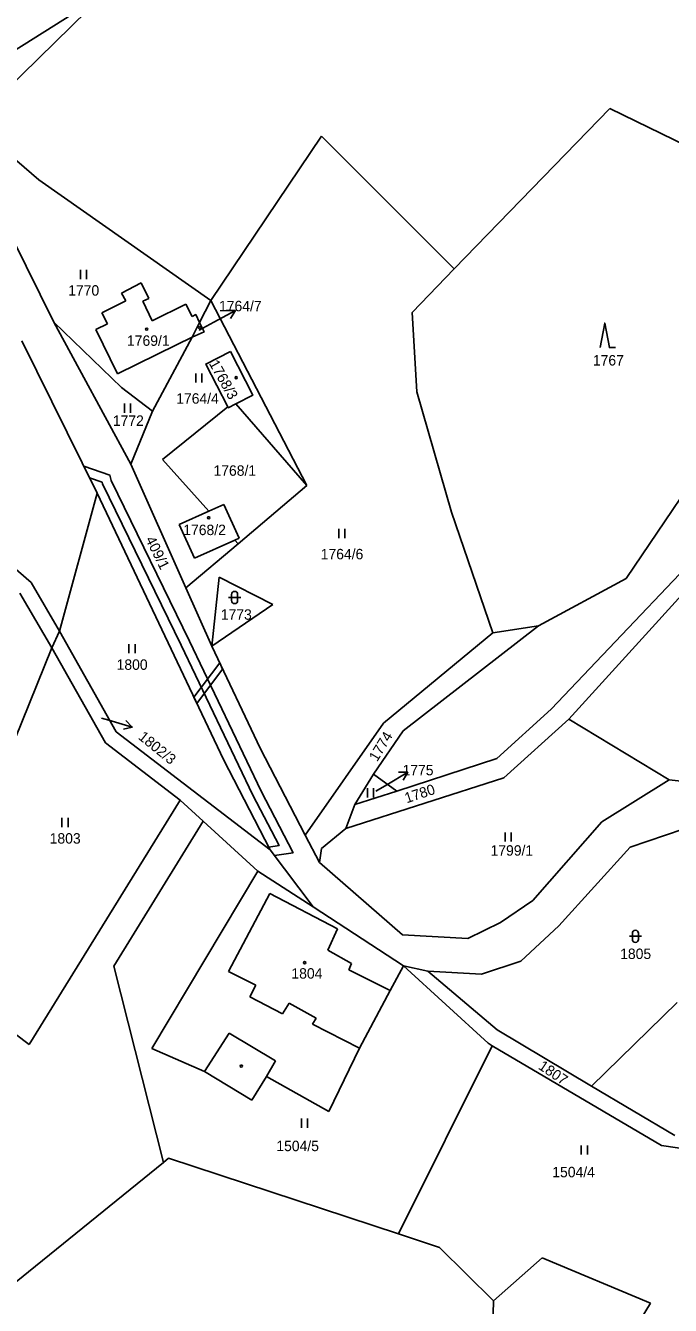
# Model space of a CAD drawing. Extents: x -670359 to -668019, y -978807 to -976674.
# Drawn here: x -669006.2 to -668901.1, y -978516 to -978307.2 of the extents above; entities that cross this region are included whole.
import ezdxf

# ---------------------------------------------------------------- set-up
doc = ezdxf.new("R2010")
doc.units = 0
for name, color, linetype in [('Hranice parcel', 7, 'Continuous'), ('Parcelní čísla', 7, 'Continuous'), ('Vnitřní kresba', 7, 'Continuous'), ('Věcná břemena k části', 7, 'Continuous'), ('Značky budov', 7, 'Continuous'), ('Značky kultur', 7, 'Continuous')]:
    doc.layers.add(name, color=color, linetype=linetype)

msp = doc.modelspace()

# ---------------------------------------------------------------- linework, layer by layer
at = {"layer": 'Hranice parcel'}
for p, q in [((-668976.34, -978386.39), (-668973.88, -978385.28)), ((-668973.88, -978385.28), (-668971.4, -978390.78)), ((-668981.19, -978388.58), (-668976.34, -978386.39)), ((-668978.67, -978394.06), (-668981.19, -978388.58)), ((-668972.11, -978391.1), (-668978.67, -978394.06)), ((-668971.4, -978390.78), (-668972.11, -978391.1)), ((-668981, -978433.55), (-668977.28, -978436.95)), ((-668977.28, -978436.95), (-668991.85, -978460.6)), ((-668977.28, -978436.95), (-668968.34, -978445.1)), ((-668991.85, -978460.6), (-668983.76, -978492.64)), ((-668930.12, -978473.61), (-668930.81, -978473.2)), ((-668945.41, -978504.31), (-668930.12, -978473.61)), ((-668930.12, -978473.61), (-668902.52, -978489.86)), ((-668983.76, -978492.64), (-668982.92, -978491.96)), ((-668982.92, -978491.96), (-668945.41, -978504.31)), ((-668983.76, -978492.64), (-669008.9, -978513.02)), ((-668945.41, -978504.31), (-668938.75, -978506.5))]:
    msp.add_line(p, q, dxfattribs=at)
for points in [[(-668993.41, -978302), (-669020.01, -978318.72)], [(-669014.9, -978323.01), (-668993.41, -978302)], [(-668910.96, -978320.68), (-668936.31, -978346.87)], [(-668898.34, -978326.82), (-668910.96, -978320.68)], [(-669004.09, -978332.32), (-669014.9, -978323.01)], [(-669001.61, -978355.56), (-669017.47, -978323.6)], [(-668976.02, -978352.01), (-668957.95, -978325.18)], [(-668957.95, -978325.18), (-668936.31, -978346.87)], [(-668976.02, -978352.01), (-669004.09, -978332.32)], [(-668943.16, -978353.95), (-668936.31, -978346.87)], [(-668990.6, -978350.81), (-668987.38, -978349.14)], [(-668987.38, -978349.14), (-668986.14, -978351.67)], [(-668875.35, -978348.67), (-668908.29, -978397.36)], [(-668993.82, -978354.03), (-668989.87, -978352.05)], [(-668989.87, -978352.05), (-668990.6, -978350.81)], [(-668986.14, -978351.67), (-668987.13, -978352.15)], [(-668987.13, -978352.15), (-668985.58, -978355.31)], [(-668976.02, -978352.01), (-668977.85, -978355.61)], [(-668976.02, -978352.01), (-668960.37, -978382.21)], [(-668992.89, -978355.82), (-668993.82, -978354.03)], [(-668985.58, -978355.31), (-668980.09, -978352.61)], [(-668980.09, -978352.61), (-668979.09, -978354.62)], [(-668979.09, -978354.62), (-668978.48, -978354.32), (-668977.85, -978355.61)], [(-668943.16, -978353.95), (-668942.42, -978366.92)], [(-668990.59, -978366.23), (-669001.61, -978355.56)], [(-668989.05, -978378.74), (-669001.61, -978355.56)], [(-668994.79, -978356.75), (-668992.89, -978355.82)], [(-668977.85, -978355.61), (-668977.12, -978357.13), (-668979.06, -978357.99)], [(-668977.85, -978355.61), (-668979.06, -978357.99)], [(-668991.22, -978363.97), (-668994.79, -978356.75)], [(-668985.54, -978370.08), (-668979.06, -978357.99)], [(-668979.06, -978357.99), (-668981.62, -978359.24)], [(-668994.57, -978383.44), (-669006.84, -978358.62)], [(-668991.22, -978363.97), (-668981.62, -978359.24)], [(-668973.25, -978369.39), (-668976.84, -978362.39), (-668972.84, -978360.35)], [(-668972.84, -978360.35), (-668969.17, -978367.46), (-668971.94, -978368.88)], [(-668985.54, -978370.08), (-668990.59, -978366.23)], [(-668942.42, -978366.92), (-668936.76, -978386.54)], [(-668971.94, -978368.88), (-668973.19, -978369.51), (-668973.25, -978369.39)], [(-668971.94, -978368.88), (-668960.37, -978382.21)], [(-668989.05, -978378.74), (-668985.54, -978370.08)], [(-668983.91, -978377.95), (-668973.25, -978369.39)], [(-669005.31, -978398.05), (-669027.43, -978378.82)], [(-668989.05, -978378.74), (-668980.09, -978398.92)], [(-668983.91, -978377.95), (-668976.34, -978386.39)], [(-668994.57, -978383.44), (-669000.72, -978405.97)], [(-668973.95, -978426.92), (-668994.57, -978383.44)], [(-668960.37, -978382.21), (-668971.58, -978391.69)], [(-668888.06, -978384.52), (-668920.5, -978418.67)], [(-668936.76, -978386.54), (-668930.05, -978406.26)], [(-668917.65, -978420.32), (-668887.22, -978386.86)], [(-668971.58, -978391.69), (-668980.09, -978398.92)], [(-668972.11, -978391.1), (-668971.58, -978391.69)], [(-669000.72, -978405.97), (-669005.31, -978398.05)], [(-668974.64, -978397.15), (-668975.87, -978408.41)], [(-668965.91, -978401.63), (-668974.64, -978397.15)], [(-668908.29, -978397.36), (-668922.59, -978405.11)], [(-669007.18, -978399.78), (-669001.97, -978408.67)], [(-668975.87, -978408.41), (-668980.09, -978398.92)], [(-668975.87, -978408.41), (-668965.91, -978401.63)], [(-669000.72, -978405.97), (-669001.97, -978408.67)], [(-668991.48, -978422.37), (-669000.72, -978405.97)], [(-668930.05, -978406.26), (-668947.84, -978420.98)], [(-668922.59, -978405.11), (-668944.66, -978422.24)], [(-668930.05, -978406.26), (-668922.59, -978405.11)], [(-669001.97, -978408.67), (-669011.67, -978432.66)], [(-668993.19, -978424.18), (-669001.97, -978408.67)], [(-668968, -978425.03), (-668975.87, -978408.41)], [(-668920.5, -978418.67), (-668929.37, -978426.75)], [(-668947.84, -978420.98), (-668960.64, -978439.24)], [(-668928.22, -978429.89), (-668917.65, -978420.32)], [(-668901.25, -978430.21), (-668917.65, -978420.32)], [(-668966.36, -978441.62), (-668991.48, -978422.37)], [(-668944.66, -978422.24), (-668949.5, -978429.27)], [(-668981, -978433.55), (-668993.19, -978424.18)], [(-668960.64, -978439.24), (-668968, -978425.03)], [(-668966.36, -978441.62), (-668973.95, -978426.92)], [(-668929.37, -978426.75), (-668945.71, -978432.06)], [(-668949.5, -978429.27), (-668952.55, -978434.26)], [(-668949.5, -978429.27), (-668945.71, -978432.06)], [(-668953.98, -978438.15), (-668928.22, -978429.89)], [(-668901.25, -978430.21), (-668912.26, -978437.05)], [(-668892.07, -978431.25), (-668901.25, -978430.21)], [(-668981, -978433.55), (-669005.65, -978473.4)], [(-668945.71, -978432.06), (-668952.55, -978434.26)], [(-668952.55, -978434.26), (-668953.98, -978438.15)], [(-668912.26, -978437.05), (-668923.52, -978449.89)], [(-668958.31, -978443.68), (-668960.64, -978439.24)], [(-668953.98, -978438.15), (-668957.96, -978441.44)], [(-668898.99, -978438.24), (-668907.61, -978441.21)], [(-668959.32, -978450.94), (-668966.36, -978441.62)], [(-668957.96, -978441.44), (-668958.31, -978443.68)], [(-668907.61, -978441.21), (-668919.27, -978454.05)], [(-668944.75, -978455.52), (-668958.31, -978443.68)], [(-668985.65, -978474.07), (-668968.34, -978445.1)], [(-668959.32, -978450.94), (-668968.34, -978445.1)], [(-668923.52, -978449.89), (-668928.79, -978453.48)], [(-668959.32, -978450.94), (-668944.6, -978460.56)], [(-668928.79, -978453.48), (-668934.12, -978456.1)], [(-668919.27, -978454.05), (-668925.46, -978459.78)], [(-668934.12, -978456.1), (-668944.75, -978455.52)], [(-668944.6, -978460.56), (-668946.75, -978464.6)], [(-668944.6, -978460.56), (-668930.81, -978473.2)], [(-668940.61, -978461.43), (-668944.6, -978460.56)], [(-668925.46, -978459.78), (-668931.9, -978461.9)], [(-669020.9, -978461.93), (-669005.65, -978473.4)], [(-668931.9, -978461.9), (-668940.61, -978461.43)], [(-668940.61, -978461.43), (-668929.33, -978470.99)], [(-668951.79, -978473.99), (-668946.75, -978464.6)], [(-668899.96, -978466.55), (-668913.96, -978480.22)], [(-668929.33, -978470.99), (-668913.96, -978480.22)], [(-668977.03, -978477.83), (-668985.65, -978474.07)], [(-668956.78, -978484.34), (-668951.79, -978473.99)], [(-668969.31, -978482.48), (-668977.03, -978477.83)], [(-668966.92, -978478.64), (-668969.31, -978482.48)], [(-668956.78, -978484.34), (-668966.92, -978478.64)], [(-668913.96, -978480.22), (-668900.33, -978488.22)], [(-668902.52, -978489.86), (-668865.32, -978495.31)], [(-668929.94, -978515.21), (-668938.75, -978506.5)], [(-668921.97, -978508.23), (-668929.94, -978515.21)], [(-668904.33, -978515.58), (-668921.97, -978508.23)], [(-668929.94, -978515.21), (-668930.2, -978525.93)], [(-668910.1, -978525.08), (-668904.33, -978515.58)]]:
    msp.add_lwpolyline(points, dxfattribs=at)
at = {"layer": 'Parcelní čísla'}
for p, q in [((-668973.52, -978353.62), (-668972.02, -978353.65)), ((-668977.9, -978356.87), (-668975.53, -978355.57)), ((-668993.86, -978420.17), (-668992.68, -978420.51)), ((-668989.88, -978420.53), (-668988.83, -978421.61)), ((-668945.4, -978428.99), (-668943.9, -978428.97)), ((-668949.12, -978432.07), (-668947.34, -978431.01))]:
    msp.add_line(p, q, dxfattribs=at)
for points in [[(-668975.53, -978355.57), (-668972.02, -978353.65), (-668972.8, -978354.93)], [(-668992.68, -978420.51), (-668988.83, -978421.61), (-668990.29, -978421.97)], [(-668947.34, -978431.01), (-668943.9, -978428.97), (-668944.64, -978430.28)]]:
    msp.add_lwpolyline(points, dxfattribs=at)
at = {"layer": 'Vnitřní kresba'}
for points in [[(-668973.15, -978461.5), (-668966.41, -978448.74)], [(-668966.41, -978448.74), (-668955.38, -978454.53)], [(-668955.38, -978454.53), (-668956.96, -978458.02)], [(-668956.96, -978458.02), (-668953.08, -978460.17)], [(-668953.08, -978460.17), (-668953.49, -978461.2)], [(-668968.71, -978463.73), (-668973.15, -978461.5)], [(-668953.49, -978461.2), (-668946.75, -978464.6)], [(-668969.66, -978465.6), (-668968.71, -978463.73)], [(-668964.34, -978468.37), (-668969.66, -978465.6)], [(-668963.27, -978466.63), (-668964.34, -978468.37)], [(-668963.27, -978466.63), (-668958.83, -978469.11)], [(-668958.83, -978469.11), (-668959.45, -978470.1)], [(-668959.45, -978470.1), (-668951.79, -978473.99)], [(-668977.03, -978477.83), (-668973.04, -978471.54)], [(-668973.04, -978471.54), (-668965.48, -978476.07)], [(-668965.48, -978476.07), (-668966.92, -978478.64)]]:
    msp.add_lwpolyline(points, dxfattribs=at)
at = {"layer": 'Věcná břemena k části'}
for p, q in [((-668978.78, -978416.73), (-668974.58, -978411.13)), ((-668974.1, -978412.15), (-668978.3, -978417.75)), ((-668974.58, -978411.13), (-668974.1, -978412.15)), ((-668978.3, -978417.75), (-668978.78, -978416.73))]:
    msp.add_line(p, q, dxfattribs=at)
msp.add_lwpolyline([(-668993.76, -978381.63), (-668995.81, -978380.92), (-668996.76, -978379.02), (-668992.52, -978380.49), (-668992.28, -978381.36), (-668979.52, -978407.57), (-668967.81, -978432.05), (-668962.62, -978442.11), (-668965.63, -978442.58), (-668966.36, -978441.62), (-668966.57, -978441.21), (-668964.9, -978440.95), (-668969.15, -978432.71), (-668980.88, -978408.23), (-668993.68, -978381.9), (-668993.76, -978381.63)], dxfattribs=at)
at = {"layer": 'Značky budov'}
for centre in [(-668986.48, -978356.68), (-668971.89, -978364.6), (-668976.37, -978387.46), (-668960.72, -978460.04)]:
    msp.add_circle(centre, 0.175, dxfattribs=at)
at = {"layer": 'Značky kultur'}
for p, q in [((-668997.29, -978347.02), (-668997.29, -978348.52)), ((-668996.29, -978348.52), (-668996.29, -978347.02)), ((-668978.47, -978363.91), (-668978.47, -978365.41)), ((-668977.47, -978365.41), (-668977.47, -978363.91)), ((-668990.13, -978368.84), (-668990.13, -978370.34)), ((-668989.13, -978370.34), (-668989.13, -978368.84)), ((-668955.15, -978389.28), (-668955.15, -978390.78)), ((-668954.15, -978390.78), (-668954.15, -978389.28)), ((-668972.65, -978399.97), (-668972.65, -978400.97)), ((-668971.65, -978399.97), (-668971.65, -978400.97)), ((-668973.15, -978400.47), (-668971.15, -978400.47)), ((-668989.39, -978408.07), (-668989.39, -978409.57)), ((-668988.39, -978409.57), (-668988.39, -978408.07)), ((-668950.49, -978431.6), (-668950.49, -978433.1)), ((-668949.49, -978433.1), (-668949.49, -978431.6)), ((-669000.31, -978436.42), (-669000.31, -978437.92)), ((-668999.31, -978437.92), (-668999.31, -978436.42)), ((-668928.02, -978438.8), (-668928.02, -978440.3)), ((-668927.02, -978440.3), (-668927.02, -978438.8)), ((-668907.76, -978455.75), (-668905.76, -978455.75)), ((-668907.26, -978455.25), (-668907.26, -978456.25)), ((-668906.26, -978455.25), (-668906.26, -978456.25)), ((-668961.24, -978485.47), (-668961.24, -978486.97)), ((-668960.24, -978486.97), (-668960.24, -978485.47)), ((-668915.6, -978489.86), (-668915.6, -978491.36)), ((-668914.6, -978491.36), (-668914.6, -978489.86))]:
    msp.add_line(p, q, dxfattribs=at)
msp.add_lwpolyline([(-668912.52, -978359.71), (-668911.77, -978355.71), (-668911.02, -978359.71), (-668910.02, -978359.71)], dxfattribs=at)
for centre in [(-668986.48, -978356.68), (-668977.88, -978356.43), (-668971.89, -978364.6), (-668976.37, -978387.46), (-668960.72, -978460.04), (-668971.05, -978476.92)]:
    msp.add_circle(centre, 0.175, dxfattribs=at)
for centre, start, end in [((-668972.15, -978399.97), 0, 180), ((-668972.15, -978400.97), 180, 0), ((-668906.76, -978455.25), 0, 180), ((-668906.76, -978456.25), 180, 0)]:
    msp.add_arc(centre, 0.5, start, end, dxfattribs=at)

# ---------------------------------------------------------------- texts
at = {"layer": 'Parcelní čísla'}
for s, height, p in [('1770', 1.7, (-668999.29, -978351.22)), ('1764/7', 1.7, (-668974.69, -978353.77)), ('1769/1', 1.7, (-668989.7, -978359.41)), ('1764/7', 0.1, (-668978.14, -978356.87)), ('1767', 1.7, (-668913.71, -978362.62)), ('1764/4', 1.7, (-668981.67, -978368.85)), ('1772', 1.7, (-668992.01, -978372.47)), ('1768/1', 1.7, (-668975.59, -978380.61)), ('1768/2', 1.7, (-668980.52, -978390.29)), ('1764/6', 1.7, (-668958.1, -978394.24)), ('1773', 1.7, (-668974.4, -978404.1)), ('1800', 1.7, (-668991.39, -978412.27)), ('1775', 1.7, (-668944.76, -978429.48)), ('1775', 0.1, (-668949.12, -978432.07)), ('1803', 1.7, (-669002.31, -978440.62)), ('1799/1', 1.7, (-668930.4, -978442.59)), ('1805', 1.7, (-668909.26, -978459.45)), ('1804', 1.7, (-668962.88, -978462.65)), ('1504/5', 1.7, (-668965.34, -978490.8)), ('1504/4', 1.7, (-668920.33, -978495.06))]:
    msp.add_text(s, height=height, dxfattribs=at).set_placement(p)
for s, height, rotation, p in [('1768/3', 1.7, 299.2382, (-668976.38, -978362.28)), ('409/1', 1.7, 296.2705, (-668986.72, -978390.98)), ('1802/3', 0.1, 320.9242, (-668994.04, -978420.02)), ('1802/3', 1.7, 320.9242, (-668987.98, -978423.45)), ('1774', 1.7, 59.0585, (-668948.89, -978427.36)), ('1780', 1.7, 18.3175, (-668944.08, -978434.06)), ('1807', 1.7, 325.8403, (-668922.74, -978477.28))]:
    msp.add_text(s, height=height, rotation=rotation, dxfattribs=at).set_placement(p)

doc.saveas('drawing.dxf')
